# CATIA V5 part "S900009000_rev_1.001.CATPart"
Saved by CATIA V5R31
Part number: 900009000
Revision: 1
Nomenclature: NUT-WELD
Source: Unknown
Property "部品番号(A社)": "900009000"
Property "部品名称(A社)": "NUT-WELD"
Property "Version(A社)": "1"
Property "材質(A社)": "SWRM10"
Bounding box of the stored display mesh (mm): x -5.3 to 5.3, y -5.3 to 5.3, z -1 to 5
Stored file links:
  \\solize.local\damia\dept\DDE_Design\10_order\2305701_JAMA_変換検証STEP3_お手本モデル作成\work\02_マツダ_板金\10_CATIA_V5\231211\S900009000_rev_1.001.CATPart
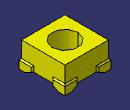
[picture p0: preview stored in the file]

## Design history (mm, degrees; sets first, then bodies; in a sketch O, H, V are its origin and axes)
Body1 "MANIFOLD_SOLID_BREP #9751" (main body)
  Solid1: solid without history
